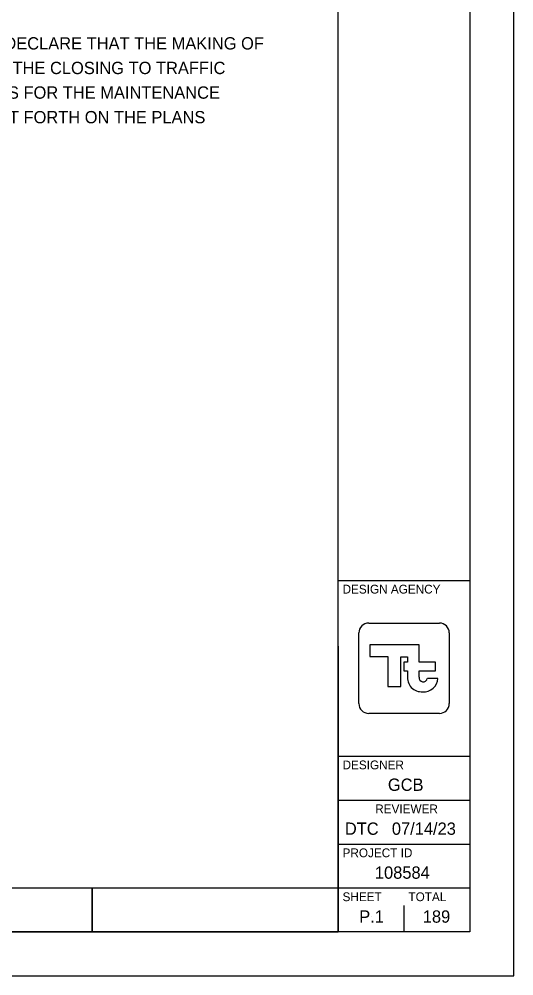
# Model space of a CAD drawing. Extents: x 0 to 40.2, y 0 to 22.
# Drawn here: x 28.37 to 34, y 0 to 10.89 of the extents above; entities that cross this region are included whole.
import ezdxf

# ---------------------------------------------------------------- set-up
doc = ezdxf.new("R2010")
doc.units = 0
for name, color, linetype in [('GM_X_Adjacent_County', 7, 'Continuous'), ('GM_X_Adjacent_County_Text', 7, 'Continuous'), ('GM_X_County', 7, 'Continuous'), ('GM_X_Township', 7, 'Continuous')]:
    doc.layers.add(name, color=color, linetype=linetype)

msp = doc.modelspace()

# ---------------------------------------------------------------- linework, layer by layer
at = {"layer": 'GM_X_Adjacent_County'}
for p, q in [((32, 3.75), (32, 0.5)), ((32.75, 3.5), (32.75, 3.5)), ((32.791, 3.415), (32.791, 3.415)), ((33.136, 3.385), (33.015, 3.385)), ((32.75, 0.5), (32.75, 0.8)), ((32.375, 0.675), (32.375, 0.675)), ((26.4, 0.5), (29.2, 0.5)), ((29.2, 0.5), (32, 0.5))]:
    msp.add_line(p, q, dxfattribs=at)
for points in [[(32.348, 4.014), (33.152, 4.014)], [(32.236, 3.099), (32.236, 3.901)], [(33.264, 3.901), (33.264, 3.099)], [(32.922, 3.399), (32.922, 3.47), (33.107, 3.47), (33.107, 3.568), (32.922, 3.568), (32.922, 3.768), (32.361, 3.768), (32.361, 3.632), (32.566, 3.632), (32.566, 3.294), (32.715, 3.294), (32.715, 3.63), (32.79, 3.63), (32.79, 3.568), (32.748, 3.568), (32.748, 3.47), (32.79, 3.47), (32.79, 3.415), (32.791, 3.415)], [(33.152, 2.986), (32.348, 2.986)]]:
    msp.add_lwpolyline(points, dxfattribs=at)
for points in [[(26.4, 0.5), (26.4, 1), (29.2, 1), (29.2, 0.5)], [(29.2, 0.5), (29.2, 1), (32, 1), (32, 0.5)]]:
    msp.add_lwpolyline(points, close=True, dxfattribs=at)
for centre, radius, start, end in [((32.348, 3.901), 0.113, 90, 180), ((33.152, 3.901), 0.113, 360, 90), ((32.949, 3.392), 0.16, 171.8856, 274.8323), ((32.968, 3.392), 0.0473, 171.8856, 350.9243), ((32.976, 3.392), 0.16, 265.1677, 357.3201), ((32.348, 3.099), 0.113, 180, 270), ((33.152, 3.099), 0.113, 270, 360)]:
    msp.add_arc(centre, radius, start, end, dxfattribs=at)
at = {"layer": 'GM_X_County'}
msp.add_lwpolyline([(0, 0), (34, 0), (34, 22), (0, 22)], close=True, dxfattribs=at)
at = {"layer": 'GM_X_Township'}
for p, q in [((32, 0.5), (32, 21.5)), ((32, 4.5), (33.5, 4.5)), ((32, 2.5), (33.5, 2.5)), ((32, 2), (33.5, 2)), ((32, 1.5), (33.5, 1.5)), ((32, 1), (33.5, 1))]:
    msp.add_line(p, q, dxfattribs=at)
msp.add_lwpolyline([(1.5, 21.5), (33.5, 21.5), (33.5, 0.5), (1.5, 0.5)], close=True, dxfattribs=at)

# ---------------------------------------------------------------- texts
at = {"layer": 'GM_X_Adjacent_County'}
for s, height, p in [('DESIGN AGENCY', 0.1, (32.05, 4.35)), ('DESIGNER', 0.1, (32.05, 2.35)), ('GCB', 0.14, (32.566, 2.105)), ('REVIEWER', 0.1, (32.422, 1.85)), ('DTC', 0.14, (32.076, 1.605)), ('07/14/23', 0.14, (32.611, 1.605)), ('PROJECT ID', 0.1, (32.05, 1.35)), ('108584', 0.14, (32.418, 1.105)), ('SHEET', 0.1, (32.05, 0.85)), ('TOTAL', 0.1, (32.8, 0.85)), ('P.1', 0.14, (32.24, 0.605)), ('189', 0.14, (32.963, 0.605))]:
    msp.add_text(s, height=height, dxfattribs=at).set_placement(p)
at = {"layer": 'GM_X_Adjacent_County_Text'}
for s, p in [('I HEREBY APPROVE THESE PLANS AND DECLARE THAT THE MAKING OF', (24.528, 10.54)), ('THIS IMPROVEMENT WILL NOT REQUIRE THE CLOSING TO TRAFFIC', (24.528, 10.26)), ('OF THE HIGHWAY AND THAT PROVISIONS FOR THE MAINTENANCE', (24.528, 9.98)), ('AND SAFETY OF TRAFFIC WILL BE AS SET FORTH ON THE PLANS', (24.528, 9.7))]:
    msp.add_text(s, height=0.14, dxfattribs=at).set_placement(p)

doc.saveas('drawing.dxf')
